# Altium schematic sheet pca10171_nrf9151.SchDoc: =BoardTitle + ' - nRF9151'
size A3; Organization: Nordic Semiconductor; DocumentNumber: 2; SheetNumber: 2; SheetTotal: 10; CompanyName: Nordic Semiconductor; DocumentSize: A3
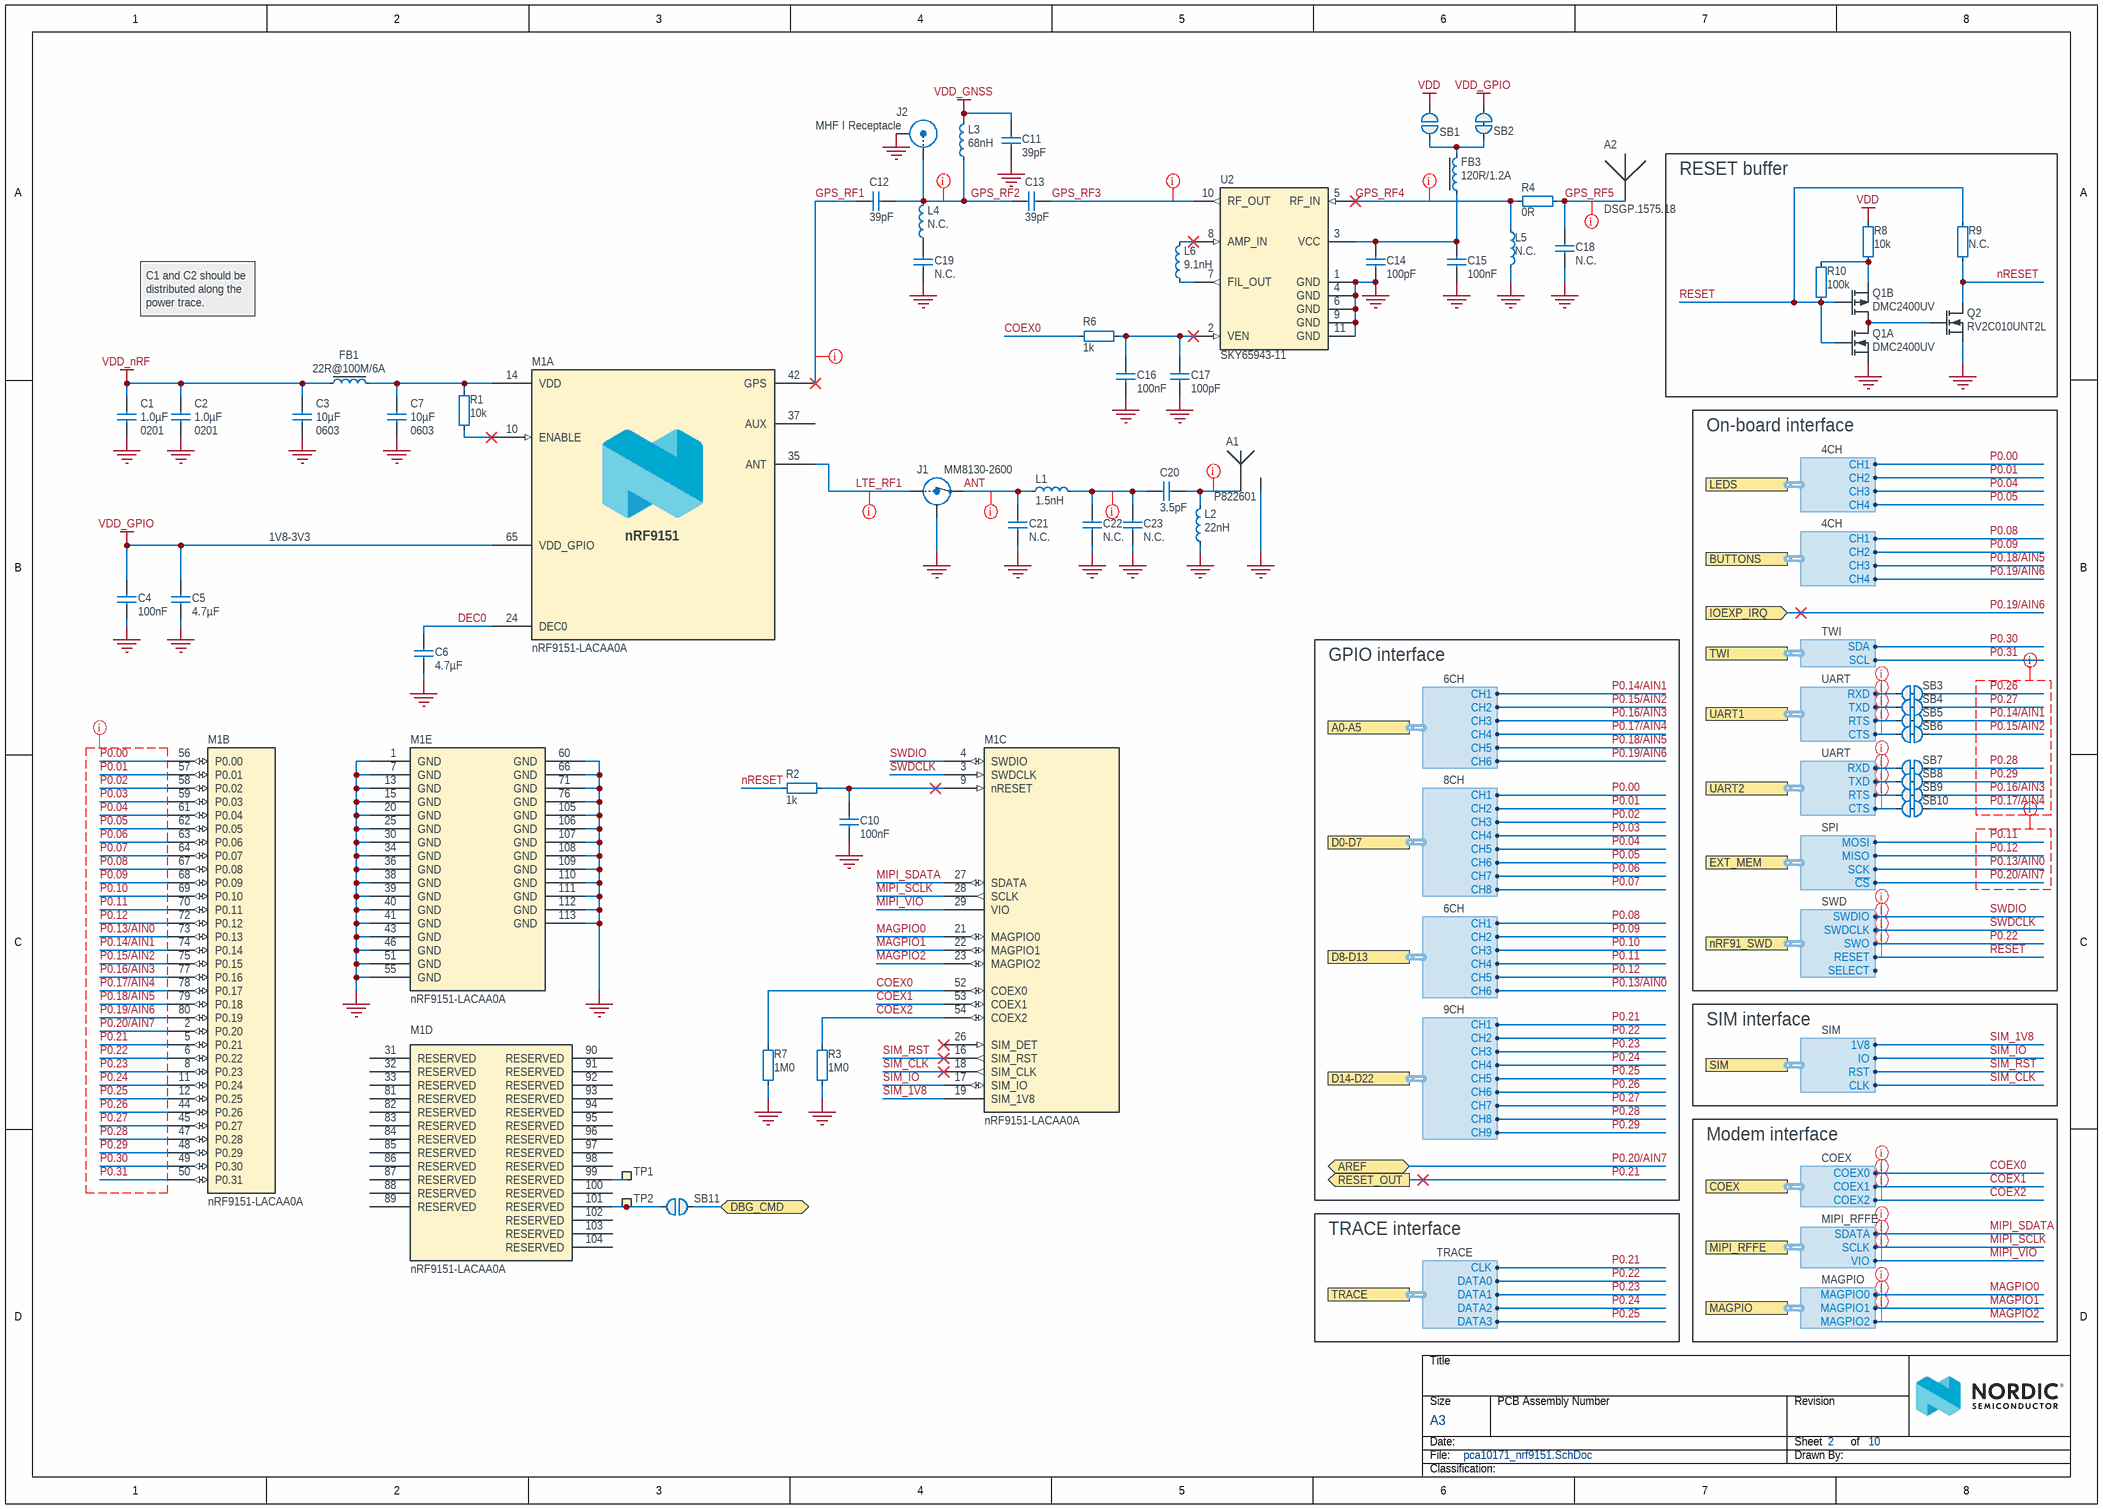
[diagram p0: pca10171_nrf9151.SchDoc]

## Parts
A1  P822601  [P822601]
A2  DSGP.1575.18  [DSGP.1575.18.4.C.02]
C1  1.0µF  Footprint Doc: 0201  [CAPC0603X03L_C]
C2  1.0µF  Footprint Doc: 0201  [CAPC0603X03L_C]
C3  10µF  Footprint Doc: 0603  [CAPC1608X06L]
C4  100nF  [CAPC0603X03L_C]
C5  4.7µF  [CAPC1005X04L]
C6  4.7µF  [CAPC1005X04L]
C7  10µF  Footprint Doc: 0603  [CAPC1608X06L]
C10  100nF  [CAPC0603X03L_C]
C11  39pF  [CAPC0603X03L_C]
C12  39pF  [CAPC0603X03L_C]
C13  39pF  [CAPC0603X03L_C]
C14  100pF  [CAPC0603X03L_C]
C15  100nF  [CAPC0603X03L_C]
C16  100nF  [CAPC0603X03L_C]
C17  100pF  [CAPC0603X03L_C]
C18  N.C.  [CAPC1005X04L_NC]
C19  N.C.  [CAPC0603X03L_C_NC]
C20  3.5pF  [CAPC0603X03L_C]
C21  N.C.  [CAPC0603X03L_C_NC]
C22  N.C.  [CAPC0603X03L_C_NC]
C23  N.C.  [CAPC0603X03L_C_NC]
FB1  22R@100M/6A  [INDC1608X06L]
FB3  120R/1.2A  [INDC1005X04L]
J1  MM8130-2600  [COAXIAL-SWF]
J2  MHF I Receptacle  [COAXIAL RF U.FL-R-SMT-1]
L1  1.5nH  [INDC0603X03L_C]
L2  22nH  [INDC0603X03L_C]
L3  68nH  [INDC1005X04L_WW]
L4  N.C.  [INDC1005X04L_NC]
L5  N.C.  [INDC1005X04L_NC]
L6  9.1nH  [INDC1005X04L_WW]
M1  nRF9151-LACAA0A  [LGA50P1210X1110X130-113N]  (parts A,B,C,D,E of 5)
Q1  DMC2400UV  [SOTFL50P162X60-6N]  (parts A,B of 2)
Q2  RV2C010UNT2L  [DFN65P100X40-3L]
R1  10k  [RESC0603X03L_C]
R2  1k  [RESC0603X03L_C]
R3  1M0  [RESC0603X03L_C]
R4  0R  [RESC1005X04L]
R6  1k  [RESC0603X03L_C]
R7  1M0  [RESC0603X03L_C]
R8  10k  [RESC0603X03L_C]
R9  N.C.  [RESC0603X03L_C_NC]
R10  100k  [RESC0603X03L_C]
SB1  Solderbridge  [Solderbridge]  (value not drawn)  (no BOM)
SB2  Solderbridge  [Solderbridge_Shorted]  (value not drawn)  (net tie, no BOM)
SB3  Solderbridge  [Solderbridge_Shorted]  (value not drawn)  (net tie, no BOM)
SB4  Solderbridge  [Solderbridge_Shorted]  (value not drawn)  (net tie, no BOM)
SB5  Solderbridge  [Solderbridge_Shorted]  (value not drawn)  (net tie, no BOM)
SB6  Solderbridge  [Solderbridge_Shorted]  (value not drawn)  (net tie, no BOM)
SB7  Solderbridge  [Solderbridge_Shorted]  (value not drawn)  (net tie, no BOM)
SB8  Solderbridge  [Solderbridge_Shorted]  (value not drawn)  (net tie, no BOM)
SB9  Solderbridge  [Solderbridge_Shorted]  (value not drawn)  (net tie, no BOM)
SB10  Solderbridge  [Solderbridge_Shorted]  (value not drawn)  (net tie, no BOM)
SB11  Solderbridge  [Solderbridge]  (value not drawn)  (no BOM)
TP1  Ø1.0mm,SMD  [TP_SMD_D1.0mm]  (value not drawn)  (no BOM)
TP2  Ø1.0mm,SMD  [TP_SMD_D1.0mm]  (value not drawn)  (no BOM)
U2  SKY65943-11  [SKY65943-11]

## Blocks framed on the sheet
RESET buffer: Q1 Q2 R8-R10
On-board interface: SB3-SB10

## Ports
A0-A5 (harness 6CH), AREF (bidir), BUTTONS (harness 4CH), COEX (harness COEX), D0-D7 (harness 8CH), D8-D13 (harness 6CH), D14-D22 (harness 9CH), DBG_CMD (bidir), EXT_MEM (harness SPI), IOEXP_IRQ (in), LEDS (harness 4CH), MAGPIO (harness MAGPIO), MIPI_RFFE (harness MIPI_RFFE), nRF91_SWD (harness SWD), RESET_OUT (out), SIM (harness SIM), TRACE (harness TRACE), TWI (harness TWI), UART1 (harness UART), UART2 (harness UART)

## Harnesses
COEX: COEX0, COEX2, COEX1
UART: RTS, CTS, RXD, TXD
SIM: CLK, IO, 1V8, RST
SWD: SWDIO, SWDCLK, SWO, RESET, SELECT
TWI: SCL, SDA
TRACE: CLK, DATA0, DATA1, DATA3, DATA2
SPI: SCK, ~{CS}, MOSI, MISO
MIPI_RFFE: SDATA, VIO, SCLK
MAGPIO: MAGPIO0, MAGPIO2, MAGPIO1
4CH: CH1, CH2, CH3, CH4
6CH: CH1, CH2, CH3, CH4, CH5, CH6
8CH: CH1, CH2, CH3, CH4, CH5, CH6, CH7, CH8
9CH: CH1, CH2, CH3, CH4, CH5, CH6, CH7, CH8, CH9

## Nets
GND: A1.2 A2.2(GND) C1.2 C2.2 C3.2 C4.2 C5.2 C6.2 C7.2 C10.2 C11.1 C14.1 C15.1 C16.1 C17.1 C18.2 C19.1 C21.1 C22.1 C23.1 J1.2(Shield) J2.2(Y) L2.1 L5.2 M1.1(GND) M1.7(GND) M1.13(GND) M1.15(GND) M1.20(GND) M1.25(GND) M1.30(GND) M1.34(GND) M1.36(GND) M1.38(GND) M1.39(GND) M1.40(GND) M1.41(GND) M1.43(GND) M1.46(GND) M1.51(GND) M1.55(GND) M1.60(GND) M1.66(GND) M1.71(GND) M1.76(GND) M1.105(GND) M1.106(GND) M1.107(GND) M1.108(GND) M1.109(GND) M1.110(GND) M1.111(GND) M1.112(GND) M1.113(GND) Q1.1(S1) Q2.2(S) R3.1 R7.1 U2.1(GND) U2.4(GND) U2.6(GND) U2.9(GND) U2.11(GND)
VDD: R8.1 SB1.1
VDD_GNSS: C11.2 L3.1
VDD_GPIO: C4.1 C5.1 M1.65(VDD_GPIO) SB2.1
VDD_nRF: C1.1 C2.1 C3.1 FB1.1
ANT: C21.2 J1.3(OUT) L1.1
COEX0: M1.52(COEX0) R6.1 R7.2 ; port COEX.COEX0
COEX1: M1.53(COEX1) ; port COEX.COEX1
COEX2: M1.54(COEX2) R3.2 ; port COEX.COEX2
DBG_CMD: SB11.1 ; port DBG_CMD
DEC0: C6.1 M1.24(DEC0)
GPS_RF1: C12.2 M1.42(GPS)
GPS_RF2: C12.1 C13.2 J2.1(X) L3.2 L4.1
GPS_RF3: C13.1 U2.10(RF_OUT)
GPS_RF4: L5.1 R4.1 U2.5(RF_IN)
GPS_RF5: A2.1 C18.1 R4.2
LTE_RF1: J1.1(IN) M1.35(ANT)
MAGPIO0: M1.21(MAGPIO0) ; port MAGPIO.MAGPIO0
MAGPIO1: M1.22(MAGPIO1) ; port MAGPIO.MAGPIO1
MAGPIO2: M1.23(MAGPIO2) ; port MAGPIO.MAGPIO2
MIPI_SCLK: M1.28(SCLK) ; port MIPI_RFFE.SCLK
MIPI_SDATA: M1.27(SDATA) ; port MIPI_RFFE.SDATA
MIPI_VIO: M1.29(VIO) ; port MIPI_RFFE.VIO
nRESET: Q2.3(D) R2.1 R9.2
P0.00: M1.56(P0.00) ; port LEDS.CH1, port D0-D7.CH1
P0.01: M1.57(P0.01) ; port LEDS.CH2, port D0-D7.CH2
P0.02: M1.58(P0.02) ; port D0-D7.CH3
P0.03: M1.59(P0.03) ; port D0-D7.CH4
P0.04: M1.61(P0.04) ; port LEDS.CH3, port D0-D7.CH5
P0.05: M1.62(P0.05) ; port LEDS.CH4, port D0-D7.CH6
P0.06: M1.63(P0.06) ; port D0-D7.CH7
P0.07: M1.64(P0.07) ; port D0-D7.CH8
P0.08: M1.67(P0.08) ; port BUTTONS.CH1, port D8-D13.CH1
P0.09: M1.68(P0.09) ; port BUTTONS.CH2, port D8-D13.CH2
P0.10: M1.69(P0.10) ; port D8-D13.CH3
P0.11: M1.70(P0.11) ; port EXT_MEM.MOSI, port D8-D13.CH4
P0.12: M1.72(P0.12) ; port EXT_MEM.MISO, port D8-D13.CH5
P0.13/AIN0: M1.73(P0.13) ; port EXT_MEM.SCK, port D8-D13.CH6
P0.14/AIN1: M1.74(P0.14) SB5.1 ; port A0-A5.CH1
P0.15/AIN2: M1.75(P0.15) SB6.1 ; port A0-A5.CH2
P0.16/AIN3: M1.77(P0.16) SB9.1 ; port A0-A5.CH3
P0.17/AIN4: M1.78(P0.17) SB10.1 ; port A0-A5.CH4
P0.18/AIN5: M1.79(P0.18) ; port BUTTONS.CH3, port A0-A5.CH5
P0.19/AIN6: M1.80(P0.19) ; port IOEXP_IRQ, port BUTTONS.CH4, port A0-A5.CH6
P0.20/AIN7: M1.2(P0.20) ; port AREF, port EXT_MEM.~{CS}
P0.21: M1.5(P0.21) ; port RESET_OUT, port TRACE.CLK, port D14-D22.CH1
P0.22: M1.6(P0.22) ; port nRF91_SWD.SWO, port TRACE.DATA0, port D14-D22.CH2
P0.23: M1.8(P0.23) ; port TRACE.DATA1, port D14-D22.CH3
P0.24: M1.11(P0.24) ; port TRACE.DATA2, port D14-D22.CH4
P0.25: M1.12(P0.25) ; port TRACE.DATA3, port D14-D22.CH5
P0.26: M1.44(P0.26) SB3.1 ; port D14-D22.CH6
P0.27: M1.45(P0.27) SB4.1 ; port D14-D22.CH7
P0.28: M1.47(P0.28) SB7.1 ; port D14-D22.CH8
P0.29: M1.48(P0.29) SB8.1 ; port D14-D22.CH9
P0.30: M1.49(P0.30) ; port TWI.SDA
P0.31: M1.50(P0.31) ; port TWI.SCL
RESET: Q1.2(G1) Q1.5(G2) R9.1 R10.1 ; port nRF91_SWD.RESET
SIM_1V8: M1.19(SIM_1V8) ; port SIM.1V8
SIM_CLK: M1.18(SIM_CLK) ; port SIM.CLK
SIM_IO: M1.17(SIM_IO) ; port SIM.IO
SIM_RST: M1.16(SIM_RST) ; port SIM.RST
SWDCLK: M1.3(SWDCLK) ; port nRF91_SWD.SWDCLK
SWDIO: M1.4(SWDIO) ; port nRF91_SWD.SWDIO
NetA1_1: A1.1 C20.2 L2.2
NetC7_1: C7.1 FB1.2 M1.14(VDD) R1.1
NetC10_1: C10.1 M1.9(nRESET) R2.2
NetC14_2: C14.2 C15.2 FB3.1 U2.3(VCC)
NetC16_2: C16.2 C17.2 R6.2 U2.2(VEN)
NetC19_2: C19.2 L4.2
NetC20_1: C20.1 C22.2 C23.2 L1.2
NetFB3_2: FB3.2 SB1.2 SB2.2
NetL6_1: L6.1 U2.8(AMP_IN)
NetL6_2: L6.2 U2.7(FIL_OUT)
NetM1_10: M1.10(ENABLE) R1.2
NetM1_99: M1.99(RESERVED) TP1.1
NetM1_101: M1.101(RESERVED) SB11.2 TP2.1
NetQ1_3: Q1.3(D2) Q1.6(D1) Q2.1(G)
NetQ1_4: Q1.4(S2) R8.2 R10.2
NetSB3_2: SB3.2 ; port UART1.RXD
NetSB4_2: SB4.2 ; port UART1.TXD
NetSB5_2: SB5.2 ; port UART1.RTS
NetSB6_2: SB6.2 ; port UART1.CTS
NetSB7_2: SB7.2 ; port UART2.RXD
NetSB8_2: SB8.2 ; port UART2.TXD
NetSB9_2: SB9.2 ; port UART2.RTS
NetSB10_2: SB10.2 ; port UART2.CTS

Not connected (* = marked no-connect by the designer): M1 26(SIM_DET)* 31(RESERVED) 32(RESERVED) 33(RESERVED) 37(AUX) 81(RESERVED) 82(RESERVED) 83(RESERVED) 84(RESERVED) 85(RESERVED) 86(RESERVED) 87(RESERVED) 88(RESERVED) 89(RESERVED) 90(RESERVED) 91(RESERVED) 92(RESERVED) 93(RESERVED) 94(RESERVED) 95(RESERVED) 96(RESERVED) 97(RESERVED) 98(RESERVED) 100(RESERVED) 102(RESERVED) 103(RESERVED) 104(RESERVED)

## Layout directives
net class SWD: P0.22, RESET, SWDCLK, SWDIO
net class COEX: COEX0, COEX1, COEX2, MAGPIO0, MAGPIO1, MAGPIO2, MIPI_SCLK, MIPI_SDATA, MIPI_VIO
net class GPIO: NetSB3_2, NetSB4_2, NetSB5_2, NetSB6_2, NetSB7_2, NetSB8_2, NetSB9_2, NetSB10_2, P0.00, P0.01, P0.02, P0.03, P0.04, P0.05, P0.06, P0.07, P0.08, P0.09, P0.10, P0.11, P0.12, P0.13/AIN0, P0.14/AIN1, P0.15/AIN2, P0.16/AIN3, P0.17/AIN4, P0.18/AIN5, P0.19/AIN6, P0.20/AIN7, P0.21, P0.22, P0.23, P0.24, P0.25, P0.26, P0.27, P0.28, P0.29, P0.30, P0.31
net class RF: ANT, GPS_RF1, GPS_RF2, GPS_RF3, GPS_RF4, GPS_RF5, LTE_RF1, NetA1_1, NetC20_1
net class nRF9151_UART: P0.14/AIN1, P0.15/AIN2, P0.16/AIN3, P0.17/AIN4, P0.26, P0.27, P0.28, P0.29
net class EXT_MEM: P0.11, P0.12, P0.13/AIN0, P0.20/AIN7

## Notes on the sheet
- C1 and C2 should be distributed along the power trace.
- 1V8-3V3
- GPIO interface
- SIM interface
- Modem interface
- TRACE interface

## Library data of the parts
A1 = P822601: ANTENNA PRESTTA OCTABAND LTE; Manufacturer: Ethertronics; Part number IPS: 00000009001; Part number NEMS: 100700043; Note: N.A.; Pad Count: 2; Component Status: Active
A2 = DSGP.1575.18.4.C.02: 18 x 18 mm Low Profile GPS L1 / GALILEO E1 Passive Patch Antenna; Manufacturer: Taoglas; Part number IPS: 00000007687; Part number NEMS: 100700073; Note: N.A.; Pad Count: 2; Component Status: Active
C1 C2 = C0201-1µ0-10V-X5R-GRM033R61A105ME15: Capacitor, X5R, ±20%, 10V; Manufacturer: Murata; Part number NEMS: 100200545; Artikkelnr Noca: N.A.; Pad Count: 2; Component Status: Active
C3 C7 = C0603-10µ-10V-X6S-GRM188C81A106MA73: Capacitor, Ceramic, 10µF 10V X6S 0603,±20%; Manufacturer: Murata; Part number NEMS: 100200520; Component Status: Active; Pad Count: 2; Artikkelnr Noca: N.A.
C4 C10 C15 = C0201-100n: Capacitor, X5R, ±10%; Manufacturer: N.A.; Part number IPS: 00000001248, 00000002505; Part number Norautron: 262071862; Part number NEMS: 100200078; Note: 16V; Pad Count: 2; Component Status: Active
C5 C6 = C0402-4µ7-10V-X5R: Capacitor, X5R, 10V; Manufacturer: Murata; Manufacturer Part Number: GRM155R61A475MEAAD; Part number NEMS: 100200415; Artikkelnr Noca: N.A.; Pad Count: 2; Component Status: Active
C11-C13 = C0201-39p: Capacitor, NP0, ±1%, 25V; Manufacturer: Murata; Manufacturer Part Number: GRM0335C1E390FA01; Part number IPS: 00000001668; Part number NEMS: 100200039; Artikkelnr Noca: N.A.; Pad Count: 2; Component Status: Active
C14 C17 = C0201-100p: Capacitor, NP0, ±2%, 25V; Manufacturer: Murata; Manufacturer Part Number: GRM0335C1E101GA01; Part number IPS: 00000007853; Part number NEMS: 100200044; Artikkelnr Noca: N.A.; Pad Count: 2; Component Status: Active
C16 = C0201-100n: Capacitor, X5R, ±10%; Manufacturer: N.A.; Part number IPS: 00000001248, 00000002505; Part number Norautron: 262071862; Part number NEMS: 100200078; Assembly: Not mounted; Note: 16V; Pad Count: 2; Component Status: Active
C18 = C0402-N.C.: Not mounted; Manufacturer: N.A.; Part number NEMS: 100200105; Assembly: Not mounted; Note: Chip Cap; Pad Count: 2; Component Status: Active
C19 = C0201-N.C.: Not mounted; Manufacturer: N.A.; Part number NEMS: 100200001; Assembly: Not mounted; Note: Chip Cap; Pad Count: 2; Component Status: Active
C20 = C0201-3.5p: Capacitor, NP0, ±0.1pF, 25V; Manufacturer: Murata; Manufacturer Part Number: GJM0335C1H3R5BB01E; Part number IPS: 00000001469; Part number NEMS: 100200023; Artikkelnr Noca: N.A.; Pad Count: 2; Component Status: Active
C21-C23 = C0201-N.C.: Not mounted; Manufacturer: N.A.; Part number NEMS: 100200001; Note: Chip Cap; Assembly: Not mounted; Pad Count: 2; Component Status: Active
FB1 = FB0603-22R@100MHz-6000mA: Ferrite Bead, 22 Ohm @ 100MHz, 6000mA, 8 mOhm Max; Manufacturer: Murata; Manufacturer Part Number: BLM18SD220SN1D; Component Status: Active; Pad Count: 2; Note: Chip EMIFIL Inductor Type Chip Ferrite Bead; Artikkelnr Noca: N.A.
FB3 = FB0402-120R@100M-1200mA: Ferrite Bead, 120 Ohm @ 100MHz, 1200mA, 75 mOhm Max; Manufacturer: Murata; Manufacturer Part Number: BLM15EX121SN1; Part number NEMS: 100300416; Component Status: Active; Pad Count: 2; Note: N.A.
J1 = MM8130-2600: Coaxial Connector with Switch; Manufacturer: Murata; Part number IPS: 00000009955; Part number Norautron: 26030338; Part number NEMS: 100500400; Note: N.A.; Artikkelnr Noca: 55029011; Pad Count: 3; Component Status: Active
J2 = 20279-001E-03: Ultraminiature Coaxial Connector, 50 Ohm, SMD; Manufacturer: Wellshow; Part number IPS: 00000004436; Part number NEMS: 100500636; Note: N.A.; Pad Count: 3; Component Status: Active
L1 = L0201-1n5-HQ-Murata: Inductor, 1000mA, ±0.1ｎH, 50mOhm; Manufacturer: Murata; Manufacturer Part Number: LQP03HQ1N5B02; Part number NEMS: 100300202; Note: -55°C ~ 125°C; Artikkelnr Noca: N.A.; Pad Count: 2; Component Status: Active
L2 = L0201-22n: Chip Inductor; Manufacturer: N.A.; Part number IPS: 00000001478; Part number NEMS: 100300034; Note: High frequency chip inductor ±10%; Pad Count: 2; Component Status: Active
L3 = L0402-68n-Wirewound-Murata: Inductor, 140mA, ±2%, 1960mΩ, Q=20; Manufacturer: Murata; Manufacturer Part Number: LQW15AN68NG00; Part number IPS: 00000002494; Part number NEMS: 100300389; Note: -55°C ~ 125°C; Artikkelnr Noca: N.A.; Pad Count: 2; Component Status: Active
L4 L5 = L0402-N.C.: Not mounted; Manufacturer: N.A.; Part number NEMS: 100300037; Assembly: Not mounted; Pad Count: 2; Component Status: Active
L6 = L0402-9n1-Wirewound-Murata: Inductor, 540mA, ±2%, 140mΩ, Q=25; Manufacturer: Murata; Manufacturer Part Number: LQW15AN9N1G00; Part number IPS: 00000002497; Part number NEMS: 100300357; Note: -55°C ~ 125°C; Artikkelnr Noca: N.A.; Pad Count: 2; Component Status: Active
M1 = nRF9151-LACAA0A: Low power System-in-Package with integrated LTE-M/NB-IoT modem and GPS; Manufacturer: Nordic Semiconductor; Component Status: Active; Pad Count: 113; Note: N.A.
Q1 = DMC2400UV: Dual N & P Ch MOFET, 1.03A/0.7A, 480mOhm, 450mW; Manufacturer: Diodes Incorporated; Part number IPS: 00000007803; Part number NEMS: 101300117; Note: Dual N & P Channel Digital FET; Artikkelnr Noca: N.A.; Pad Count: 6; Component Status: Active
Q2 = RV2C010UNT2L: N-Channel MOSFET, 20V, 1A, 470mOhm, 400mW; Manufacturer: Rohm Semiconductor; Part number IPS: 00000009976; Part number Norautron: 26320026; Part number NEMS: 101300132; Note: N.A.; Artikkelnr Noca: 35010020; Pad Count: 3; Component Status: Active
R1 R8 = R0201-10k: Resistor, ±1%, 0.05W; Manufacturer: N.A.; Part number IPS: 00000001255; Part number Norautron: 26107101; Part number NEMS: 100100065; Note: Chip Res 1%; Pad Count: 2; Component Status: Active
R2 R6 = R0201-1k0: Resistor, ±1%, 0.05W; Manufacturer: N.A.; Part number IPS: 00000005786; Part number NEMS: 100100043; Note: Chip Res 1%; Pad Count: 2; Component Status: Active
R3 R7 = R0201-1M0: Resistor, ±1%, 0.05W; Manufacturer: N.A.; Part number IPS: 00000001418; Part number Norautron: 26107108; Part number NEMS: 100100093; Note: Chip Res 1%; Pad Count: 2; Component Status: Active
R4 = R0402-0R: Resistor, ±5%, 0.063W; Manufacturer: N.A.; Part number IPS: 00000007128; Part number NEMS: 100100109; Note: Chip Res 5%; Artikkelnr Noca: 27049000; Pad Count: 2; Component Status: Active
R9 = R0201-N.C.: Not mounted; Manufacturer: N.A.; Part number NEMS: 100100107; Note: Chip Res; Assembly: Not mounted; Pad Count: 2; Component Status: Active
R10 = R0201-100k: Resistor, ±1%, 0.05W; Manufacturer: N.A.; Part number IPS: 00000001419; Part number Norautron: 26108487; Part number NEMS: 100100080; Note: Chip Res 1%; Pad Count: 2; Component Status: Active
SB1 = Solderbridge: Manufacturer: N.A.; Part number NEMS: 100500458; Component Status: Active; Pad Count: 2; System: Connector
SB2 = Solderbridge Shorted: Shorted Solderbridge; Manufacturer: N.A.; Part number NEMS: 100500459; Component Status: Active; Pad Count: 2; System: Connector
SB3-SB10 = Solderbridge Shorted: Shorted Solderbridge; Manufacturer: N.A.; Part number NEMS: 100500459; Pad Count: 2; Component Status: Active; System: Connector
SB11 = Solderbridge: Manufacturer: N.A.; Part number NEMS: 100500458; Pad Count: 2; Component Status: Active; System: Connector
TP1 TP2 = TP_SMD_Ø1.0MM: 1.0mm circular SMD testpad; Manufacturer: Nordic Semiconductor; Manufacturer Part Number: N.A.; Part number NEMS: 100500475; Pad Count: 1; Component Status: Active
U2 = SKY65943-11: GNSS Low-Noise Amplifier Front-End Module with Integrated Pre-Filter and Post-Filter; Manufacturer: Skyworks; Part number IPS: 00000002997; Part number NEMS: 101900584; Note: N.A.; Pad Count: 10; Component Status: Active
